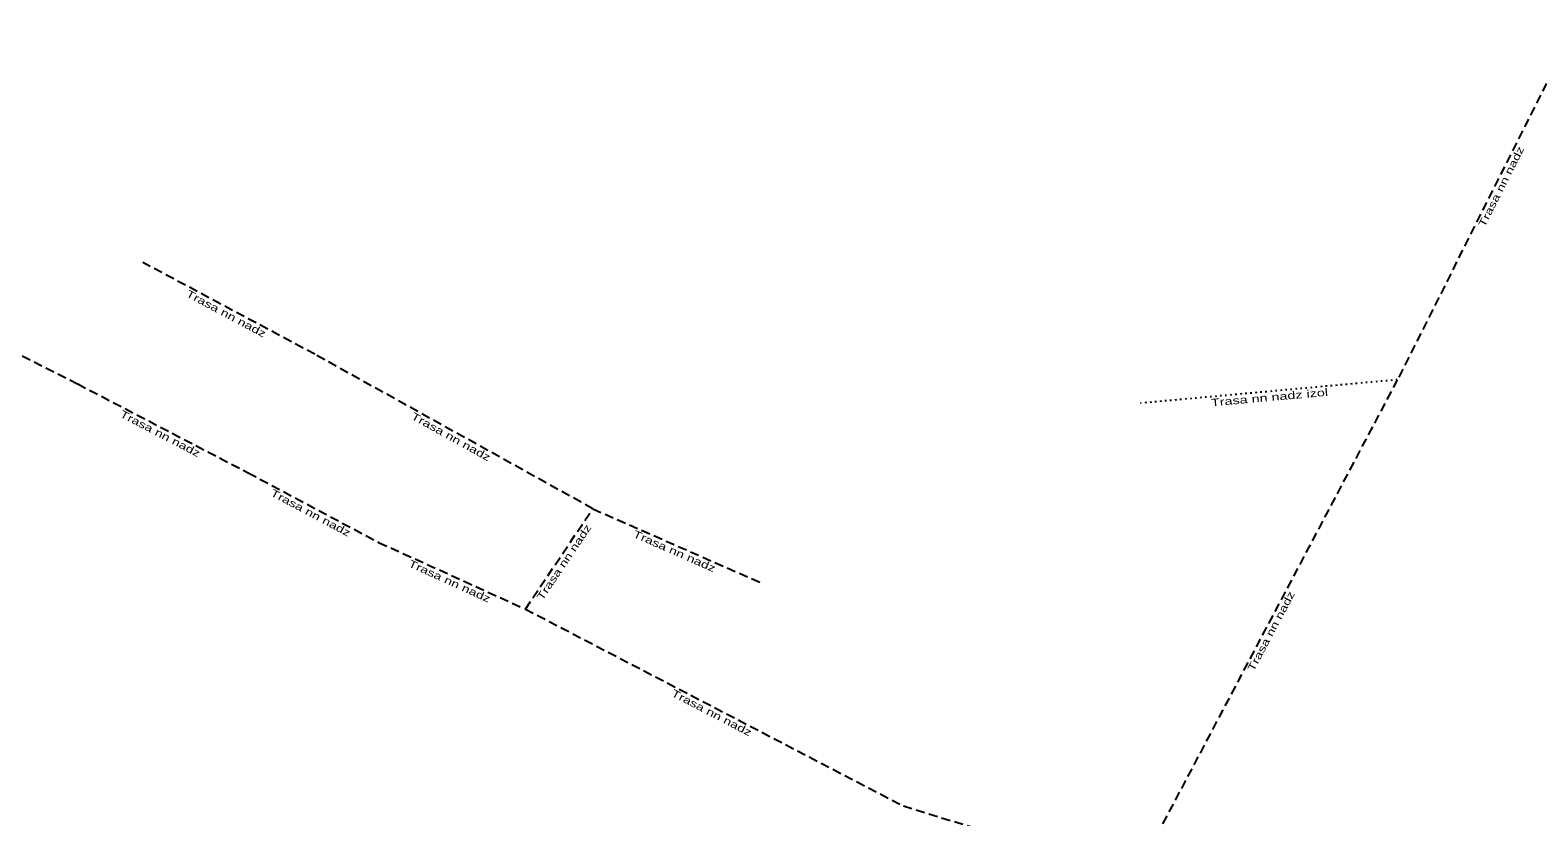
# Model space of a CAD drawing. Extents: x -733620 to -732615, y -1025255 to -1024617.
# Drawn here: x -733025.6 to -732923.9, y -1024868.1 to -1024815 of the extents above; entities that cross this region are included whole.
import ezdxf
from ezdxf.enums import TextEntityAlignment as Align

# ---------------------------------------------------------------- set-up
doc = ezdxf.new("R2010")
doc.units = 0
doc.header["$LTSCALE"] = 0.2
doc.linetypes.add('DOTTED', pattern=[1.5, 0.3, -1.2])
doc.linetypes.add('MEDIUM_DASHED', pattern=[4.5, 3, -1.5])
doc.layers.add('11', color=7, linetype='MEDIUM_DASHED', lineweight=25)
doc.layers.add('20', color=7, linetype='Continuous')

msp = doc.modelspace()

# ---------------------------------------------------------------- linework, layer by layer
at = {"layer": '11'}
for p, q in [((-732920.07, -1024812.17), (-732933.38, -1024838.62)), ((-733039, -1024830.5), (-733022.4, -1024838.9)), ((-733006.4, -1024836.9), (-733018, -1024830.7)), ((-732987.65, -1024847.33), (-733006.4, -1024836.9)), ((-733022.4, -1024838.9), (-733010.9, -1024844.9)), ((-732933.38, -1024838.62), (-732951.106, -1024872.192)), ((-732992.2, -1024854.1), (-732987.65, -1024847.33)), ((-732987.65, -1024847.33), (-732976.32, -1024852.32)), ((-732992.2, -1024854.1), (-732966.7, -1024867.4)), ((-732966.7, -1024867.4), (-732951.11, -1024872.19))]:
    msp.add_line(p, q, dxfattribs=at)
at = {"layer": '11', "linetype": 'DOTTED'}
msp.add_line((-732933.38, -1024838.62), (-732950.7, -1024840.2), dxfattribs=at)
at = {"layer": '11'}
msp.add_lwpolyline([(-733010.9, -1024844.9), (-733002.1, -1024849.6), (-732992.2, -1024854.1)], dxfattribs=at)

# ---------------------------------------------------------------- texts
at = {"layer": '20'}
for s, rotation, width, p in [('Trasa nn nadz', 63.288, 1.4, (-732926.1439, -1024825.6869)), ('Trasa nn nadz', 331.876, 1.4, (-733012.5063, -1024834.3729)), ('Trasa nn nadz izol', 5.212, 1.45, (-732941.9802, -1024840.0567)), ('Trasa nn nadz', 332.447, 1.4, (-733016.9501, -1024842.476)), ('Trasa nn nadz', 330.914, 1.4, (-732997.34, -1024842.683)), ('Trasa nn nadz', 331.894, 1.4, (-733006.8053, -1024847.8229)), ('Trasa nn nadz', 56.096, 1.4, (-732989.3845, -1024851.077)), ('Trasa nn nadz', 336.23, 1.4, (-732982.2463, -1024850.419)), ('Trasa nn nadz', 335.556, 1.4, (-732997.419, -1024852.4409)), ('Trasa nn nadz', 62.165, 1.4, (-732941.6682, -1024855.7092)), ('Trasa nn nadz', 332.455, 1.4, (-732979.7501, -1024861.3256))]:
    msp.add_text(s, height=0.5, rotation=rotation, dxfattribs=dict(at, width=width)).set_placement(p, align=Align.CENTER)

doc.saveas('drawing.dxf')
